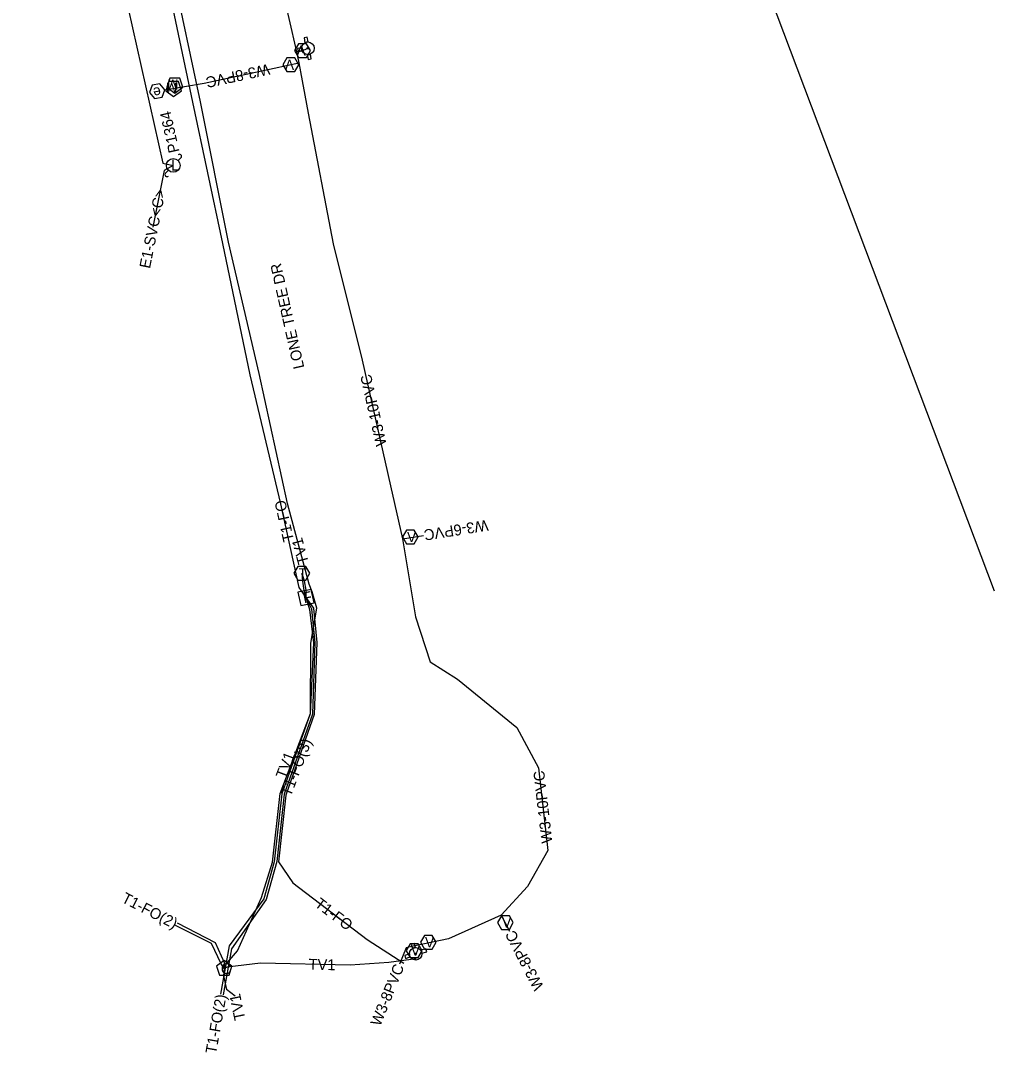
# Model space of a CAD drawing. Extents: x 2336688 to 2352634, y 362473 to 369571.
# Drawn here: x 2348334.6 to 2348691.6, y 367005.4 to 367383.7 of the extents above; entities that cross this region are included whole.
import ezdxf

# ---------------------------------------------------------------- set-up
doc = ezdxf.new("R2010")
doc.units = 0
for name, color, linetype in [('Default', 7, 'Continuous'), ('RD_EX_DV_Prop', 7, 'Continuous'), ('RD_EX_DV_TX_Prop', 7, 'Continuous'), ('RD_EX_RW', 7, 'Continuous'), ('RD_EX_RW_TX', 7, 'Continuous'), ('RD_HC_Data_Tic', 7, 'Continuous'), ('RD_PD_CstnLmt', 7, 'Continuous'), ('RD_PD_Final_TrvlWay', 7, 'Continuous'), ('RD_Sketch2', 7, 'Continuous'), ('RD_TX_Misc1', 7, 'Continuous')]:
    doc.layers.add(name, color=color, linetype=linetype)

msp = doc.modelspace()

# ---------------------------------------------------------------- linework, layer by layer
at = {"layer": 'Default'}
msp.add_line((2348691.59, 367174.54), (2348367.83, 368033.25), dxfattribs=at)
msp.add_line((2348691.59, 367174.54), (2348367.83, 368033.25), dxfattribs=at)
msp.add_line((2348691.59, 367174.54), (2348367.83, 368033.25), dxfattribs=at)
at = {"layer": 'RD_EX_RW'}
msp.add_line((2348413.18, 367026.04), (2348410.04, 367028.4), dxfattribs=at)
at = {"layer": 'RD_EX_RW_TX'}
for points in [[(2348387.55, 367401.49), (2348397.52, 367353.79), (2348408.54, 367301.95), (2348418.59, 367253.86), (2348429.85, 367206.49), (2348436.62, 367175.89), (2348439.19, 367172.19), (2348441.93, 367168.26), (2348443.21, 367155.65), (2348442.22, 367129.33), (2348431.74, 367099.66), (2348429.05, 367075.28), (2348434.33, 367067.57), (2348461.63, 367046.79), (2348475.12, 367038.1)], [(2348479.59, 367039.71), (2348469.58, 367038.3), (2348455.36, 367037.38), (2348422.52, 367038.07), (2348410.32, 367036.58), (2348409.2, 367036.08), (2348409.64, 367037.53), (2348414.08, 367042.65), (2348422.83, 367062.13), (2348426.93, 367075.07), (2348429.71, 367100.28), (2348440.81, 367129.59), (2348440.94, 367155.42), (2348443.13, 367168.23), (2348441.44, 367174.21), (2348440.3, 367177.11), (2348432.39, 367206.64), (2348422.08, 367254.32), (2348410.82, 367302.48), (2348400.57, 367353.94), (2348390.4, 367401.66)], [(2348437.68, 367181.05), (2348437.86, 367178.15), (2348438.43, 367174.79), (2348440.46, 367167.82), (2348441.98, 367155.6), (2348440.7, 367129.5), (2348430.34, 367100.14), (2348427.54, 367075.2), (2348423.77, 367061.67), (2348410.99, 367044.51), (2348407.82, 367026.68)], [(2348437.68, 367181.05), (2348438.58, 367178.24), (2348439.14, 367174.92), (2348439.19, 367172.19), (2348441.16, 367168.06), (2348442.47, 367155.55), (2348441.59, 367129.37), (2348431.22, 367100.11), (2348428.44, 367075.41), (2348424.59, 367061.43), (2348411.84, 367043.36), (2348408.84, 367026.53)], [(2348409.2, 367036.08), (2348409.34, 367038.18), (2348405.98, 367045.56), (2348392.03, 367052.81)], [(2348409.2, 367036.08), (2348408.06, 367037.91), (2348404.55, 367045.34), (2348391.37, 367051.87)], [(2348409.2, 367036.08), (2348409, 367033.39), (2348410.04, 367028.4)]]:
    msp.add_lwpolyline(points, dxfattribs=at)
for points in [[(2348440.56, 367181.05), (2348439.12, 367183.55), (2348436.23, 367183.55), (2348434.79, 367181.05), (2348436.23, 367178.55), (2348439.12, 367178.55)], [(2348441.14, 367175.14), (2348436.24, 367174.13), (2348437.25, 367169.23), (2348442.15, 367170.24)], [(2348409.2, 367039.08), (2348406.35, 367037.01), (2348407.44, 367033.65), (2348410.97, 367033.65), (2348412.06, 367037.01)]]:
    msp.add_lwpolyline(points, close=True, dxfattribs=at)
at = {"layer": 'RD_HC_Data_Tic'}
for p, q in [((2348392.27, 367332.39), (2348393.33, 367333.45)), ((2348387.67, 367327.79), (2348388.73, 367328.86))]:
    msp.add_line(p, q, dxfattribs=at)
msp.add_circle((2348390.5, 367330.62), 2.5, dxfattribs=at)
for centre, start, end in [((2348392.8, 367333.98), 315, 135), ((2348388.2, 367327.26), 135, 315)]:
    msp.add_arc(centre, 0.75, start, end, dxfattribs=at)
at = {"layer": 'RD_PD_Final_TrvlWay'}
msp.add_lwpolyline([(2348334.56, 367457.38), (2348357.39, 367462.88), (2348364.93, 367428.99), (2348371.28, 367427.97), (2348366.1, 367423.71), (2348386.64, 367331.4), (2348390.5, 367330.62), (2348387.22, 367328.8), (2348383.03, 367308.02)], dxfattribs=at)
at = {"layer": 'RD_Sketch2'}
for p, q in [((2348439.6, 367377.65), (2348438.46, 367377.44)), ((2348438.46, 367377.44), (2348438.81, 367375.61)), ((2348439.94, 367375.87), (2348439.6, 367377.65)), ((2348437.58, 367373.76), (2348436.11, 367373.48)), ((2348436.11, 367373.48), (2348436.33, 367372.34)), ((2348436.33, 367372.34), (2348437.77, 367372.62)), ((2348439.65, 367371.26), (2348439.99, 367369.5)), ((2348441.12, 367369.71), (2348440.79, 367371.44)), ((2348439.99, 367369.5), (2348441.12, 367369.71)), ((2348474.55, 367193.74), (2348482.3, 367194.97)), ((2348510.75, 367055.64), (2348513.75, 367049.82)), ((2348478.88, 367045.25), (2348477.78, 367044.9)), ((2348477.78, 367044.9), (2348478.22, 367043.5)), ((2348479.33, 367043.82), (2348478.88, 367045.25)), ((2348477.1, 367041.48), (2348475.38, 367040.94)), ((2348475.38, 367040.94), (2348475.73, 367039.83)), ((2348483.09, 367043.37), (2348481.32, 367042.81)), ((2348481.71, 367041.72), (2348483.44, 367042.27)), ((2348483.44, 367042.27), (2348483.09, 367043.37)), ((2348475.73, 367039.83), (2348477.4, 367040.36))]:
    msp.add_line(p, q, dxfattribs=at)
for points in [[(2348427.29, 367409.06), (2348435.75, 367372.22), (2348436.53, 367368.24), (2348440.03, 367349.83), (2348449.1, 367301.87), (2348459.83, 367259.19), (2348470.14, 367213.14), (2348474.55, 367193.74), (2348479.35, 367165.06), (2348484.78, 367148.56), (2348494.77, 367142.25), (2348516.46, 367124.56), (2348524.39, 367109.68), (2348527.88, 367079.45), (2348520.45, 367066.24), (2348510.75, 367055.64), (2348491.39, 367046.96), (2348478.49, 367044.31), (2348475.95, 367043.76), (2348473.51, 367037.7)], [(2348435.75, 367372.22), (2348438.87, 367373.17), (2348439.88, 367373.56)], [(2348387.44, 367358.35), (2348401.91, 367360.82), (2348427.49, 367366.32), (2348436.53, 367368.24)]]:
    msp.add_lwpolyline(points, dxfattribs=at)
for points in [[(2348435.02, 367372.73), (2348436.46, 367370.23), (2348439.35, 367370.23), (2348440.79, 367372.73), (2348439.35, 367375.23), (2348436.46, 367375.23)], [(2348430.73, 367367.53), (2348432.18, 367365.03), (2348435.06, 367365.03), (2348436.51, 367367.53), (2348435.06, 367370.03), (2348432.18, 367370.03)], [(2348391.1, 367357.15), (2348394, 367359.25), (2348392.89, 367362.66), (2348389.3, 367362.66), (2348388.19, 367359.25)], [(2348381.75, 367357.38), (2348383.59, 367355.15), (2348386.44, 367355.64), (2348387.44, 367358.35), (2348385.6, 367360.57), (2348382.75, 367360.08)], [(2348390.65, 367355.9), (2348393.55, 367358.01), (2348392.44, 367361.42), (2348388.85, 367361.42), (2348387.74, 367358.01)], [(2348480.33, 367194.37), (2348478.89, 367196.87), (2348476, 367196.87), (2348474.56, 367194.37), (2348476, 367191.87), (2348478.89, 367191.87)], [(2348515.19, 367052.97), (2348513.75, 367055.46), (2348510.86, 367055.46), (2348509.42, 367052.97), (2348510.86, 367050.47), (2348513.75, 367050.47)], [(2348486.93, 367045.76), (2348485.49, 367048.26), (2348482.6, 367048.26), (2348481.16, 367045.76), (2348482.6, 367043.26), (2348485.49, 367043.26)], [(2348481.75, 367042.67), (2348480.3, 367045.17), (2348477.42, 367045.17), (2348475.97, 367042.67), (2348477.42, 367040.17), (2348480.3, 367040.17)]]:
    msp.add_lwpolyline(points, close=True, dxfattribs=at)
for centre, radius in [((2348439.88, 367373.56), 2.31), ((2348439.88, 367373.56), 0.289), ((2348479.41, 367041.51), 2.31), ((2348479.41, 367041.51), 0.289)]:
    msp.add_circle(centre, radius, dxfattribs=at)
for centre, start, end in [((2348439.88, 367373.56), 175.108, 204.0752), ((2348439.88, 367373.56), 88.5475, 117.5238), ((2348439.88, 367373.56), 264.2012, 293.1775), ((2348479.41, 367041.51), 180.8746, 209.8509), ((2348479.41, 367041.51), 91.7814, 120.7486), ((2348479.41, 367041.51), 5.2208, 34.1972)]:
    msp.add_arc(centre, 2.31, start, end, dxfattribs=at)

# ---------------------------------------------------------------- texts
at = {"layer": 'RD_EX_DV_Prop'}
msp.add_text('E1-SVC<C>', height=4, rotation=78.6105, dxfattribs=at).set_placement((2348381.97, 367292.6))
at = {"layer": 'RD_EX_DV_TX_Prop'}
msp.add_text('P1364', height=4, rotation=102.542, dxfattribs=at).set_placement((2348392.84, 367335.7))
at = {"layer": 'RD_EX_RW'}
for s, rotation, p in [('T1-FO', 102.4899, (2348434.85, 367193.12)), ('TV1', 104.9973, (2348440.27, 367184.94)), ('T1-FO(3)', 69.2115, (2348433.6, 367098.96)), ('TV1,', 69.2115, (2348431.72, 367105.4)), ('T1-FO(2)', 332.5418, (2348371.26, 367060.67)), ('T1-FO', 322.7303, (2348442.07, 367059.17)), ('TV1', 358.7911, (2348440.14, 367035.7)), ('T1-FO(2)', 79.8949, (2348406.22, 367004.65)), ('TV1', 101.7133, (2348416.97, 367017.58))]:
    msp.add_text(s, height=4, rotation=rotation, dxfattribs=at).set_placement(p)
at = {"layer": 'RD_EX_RW_TX'}
for s, height, p in [('T', 3.75, (2348436.47, 367179.18)), ('C', 4, (2348407.97, 367034.08))]:
    msp.add_text(s, height=height, dxfattribs=at).set_placement(p)
msp.add_text('F', height=4, rotation=11.6664, dxfattribs=at).set_placement((2348438.49, 367170))
at = {"layer": 'RD_HC_Data_Tic'}
msp.add_text('L', height=4, rotation=360, dxfattribs=at).set_placement((2348389.69, 367328.69))
at = {"layer": 'RD_PD_CstnLmt'}
for s, rotation, p in [('W3-8PVC', 192.1151, (2348425.41, 367367.89)), ('W3-10PVC', 102.6241, (2348468.82, 367228.2)), ('W3-6PVC', 189.0159, (2348505.65, 367200.7)), ('W3-10PVC', 96.5841, (2348529.57, 367082.31)), ('W3-8PVC', 117.2655, (2348526.52, 367029.41)), ('W3-8PVC', 68.0667, (2348466.4, 367014.7))]:
    msp.add_text(s, height=4, rotation=rotation, dxfattribs=at).set_placement(p)
at = {"layer": 'RD_Sketch2'}
for s, rotation, p in [('V', 180, (2348439.11, 367374.6)), ('V', 180, (2348434.83, 367369.4)), ('M', 180, (2348392.46, 367362.19)), ('e', 189.6849, (2348385.66, 367359.47)), ('M', 180, (2348392.01, 367360.94))]:
    msp.add_text(s, height=3.75, rotation=rotation, dxfattribs=at).set_placement(p)
for p in [(2348476.23, 367192.49), (2348511.09, 367051.09), (2348477.65, 367040.79), (2348482.83, 367043.89)]:
    msp.add_text('V', height=3.75, dxfattribs=at).set_placement(p)
at = {"layer": 'RD_TX_Misc1'}
msp.add_text('LONE TREE DR', height=4, rotation=102.6203, dxfattribs=at).set_placement((2348438.6, 367256.48))

doc.saveas('drawing.dxf')
